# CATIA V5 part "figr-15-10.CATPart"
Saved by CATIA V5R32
Part number: Part1
Bounding box of the stored display mesh (mm): x -50 to 50, y -32.5 to 33.5, z -52 to 1
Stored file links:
  D:\PROJECTS\Project 2022\CATIA V5 6R 2022\Resources\Part Files\c15_catia_v5_6r2022_prt\figr-15-10.CATPart
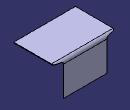
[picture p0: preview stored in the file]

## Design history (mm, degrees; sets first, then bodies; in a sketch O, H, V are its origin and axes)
SheetMetalParameters1: Thickness 1, BendRadius 4, KFactor 0.475772 {= log(min(100,max(20*SheetMetalParameters1.BendRadius,SheetMetalParameters1.Thickness)/SheetMetalParameters1.Thickness))/log(100)/2}, ReliefRadialLength 4, ReliefAxialLength 4, MinimumBendRadius 0
Body1 (main body)
  Sketch1 on xy-plane, origin (0, 0, 0), H (1, 0, 0), V (0, 1, 0)
    line L1 (-50, 32.5) -> (50, 32.5)
    line L2 (50, 32.5) -> (50, -32.5)
    line L3 (50, -32.5) -> (-50, -32.5)
    line L4 (-50, -32.5) -> (-50, 32.5)
    length L1 = 100
    length L2 = 65
    horizontal: L1 H, L3 H
    vertical: L2 V, L4 V
    symmetry: L4 L2 V, L1 L3 H
  Wall1: Thickness 1, Profile Sketch1
  d_NewWallOnEdge1: NewWallOnEdge_Edge edge [face of Wall1 | face of Wall1], NewWallOnEdge_Length 53, NewWallOnEdge_HeightLimitOffset 0, NewWallOnEdge_WidthOffset1 -15, NewWallOnEdge_WidthOffset2 -15, NewWallOnEdge_Angle 90, NewWallOnEdge_BendRadiusValue 4 {= SheetMetalParameters1.BendRadius}, NewWallOnEdge_BendTable SheetMetalParameters1, KFacteur 0.475772 {= log(min(100,max(20*d_NewWallOnEdge1.Radius,SheetMetalParameters1.Thickness)/SheetMetalParameters1.Thickness))/log(100)/2}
